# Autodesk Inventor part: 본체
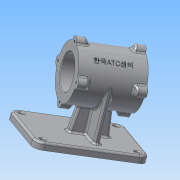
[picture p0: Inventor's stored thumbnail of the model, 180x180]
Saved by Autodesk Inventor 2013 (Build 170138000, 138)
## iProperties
Created: 2015-12
Part Number: 본체
Material: 알루미늄 6061
Document SubType Name: Modeling
Designer: Administrator
Density: 2.71 g/cm^3
Mass: 1165.53 g
Surface Area: 815.593 cm^2
Volume: 430.083 cm^3
Author: Administrator
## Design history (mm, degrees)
sketch "스케치1"
  geometry: L1 (-70, -55)-(70, -55); L2 (70, -55)-(70, 55); L3 (70, 55)-(-70, 55); L4 (-70, 55)-(-70, -55); L5 (-70, -55)-(70, 55); L6 (70, -55)-(-70, 55); 1 further point
  constraints: 12 end point, 2 midpoint, 2 parallel, 1 horizontal, 1 perpendicular
  dimensions: "d0" = 140 distance of L3.end L2.end; "d1" = 110 distance of L2.end L1.end
extrude "돌출1" new body sketch "스케치1" distance "d2" = 10; taper "d3" = 0 deg
node "작업 평면2"
sketch "스케치2"
  geometry: L1 (55, 0)-(-55, 0) reference; C1 r 37 at (0, 80); 2 further points
  constraints: 1 centre point, 1 midpoint, 1 vertical alignment
  dimensions: "d6" = 74 diameter of C1; "d8" = 80 distance from line of L1 C1.centre
extrude "돌출2" join sketch "스케치2" stored distance "d9" = 85; taper "d10" = 0 deg
sketch "스케치3"
  geometry: L1 (-52.5, 117)-(-52.5, 43) reference; L2 (32.5, 43)-(32.5, 117) reference; L3 (-52.5, 80)-(32.5, 80); L4 (-52.5, 103.5)-(-30.8, 103.5); L5 (-30.5, 103.2)-(-30.5, 101); L6 (-30.5, 101)-(10.5, 101); L7 (10.5, 101)-(10.5, 103.2); L8 (10.8, 103.5)-(32.5, 103.5); A1 r 0.3 centre (-30.8, 103.2) between (-30.5, 103.2) and (-30.8, 103.5); A2 r 0.3 centre (10.8, 103.2) between (10.8, 103.5) and (10.5, 103.2); 3 further points
  constraints: 12 end point, 6 point on line, 4 point on circle, 4 tangent, 3 parallel, 2 centre point, 2 collinear, 2 midpoint, 2 perpendicular, 1 equal radius
  dimensions: "d11" = 22 distance of L4.start point (-30.5, 103.5); "d13" = 22 distance of point (10.5, 103.5) L8.end; "d14" = 47 diameter of L8 L3; "d15" = 42 diameter of L6 L3; "d16" = 0.3 radius of A1
revolve "회전1" sketch "스케치3" stored, may be unused: angle "d17" = 90 deg
chamfer "모따기1" distance "d18" = 1; stored, may be unused: second distance "d19" = 2, angle "d20" = 45 deg
sketch "스케치4"
  geometry: L1 (70, 55)-(-70, 55) reference; L2 (-70, 55)-(-70, -55) reference; C1 r 4 at (-58, 43); C2 r 4 at (-58, -43); C3 r 4 at (58, -43); C4 r 4 at (58, 43); 1 further point
  constraints: 4 centre point, 2 horizontal alignment, 2 vertical alignment
  dimensions: "d21" = 8 diameter of C1; "d22" = 8 diameter of C2; "d23" = 8 diameter of C3; "d24" = 8 diameter of C4; "d25" = 12 distance from line of L1 C1.centre; "d26" = 12 distance from line of L2 C1.centre; "d27" = 116 distance of C4.centre C1.centre; "d28" = 86 distance of C1.centre C2.centre
extrude "돌출3" cut sketch "스케치4" stored distance "d29" = 85; taper "d30" = 0 deg
node "작업 평면3"
sketch "스케치5"
  geometry: L1 (0, 37)-(-70, 37); L2 (-70, -55)-(-70, 55) reference; L3 (0, -37)-(-70, -37); L4 (-70, 37)-(-70, -37); A1 r 37 centre (0, 0) between (0, 37) and (0, -37) reference; A2 r 37 centre (0, 0) between (0, 37) and (0, -37); 1 further point
  constraints: 6 end point, 4 point on circle, 2 point on line, 1 centre point, 1 coincident, 1 concentric, 1 horizontal, 1 parallel, 1 perpendicular, 1 tangent, 1 vertical alignment
sketch "스케치7"
  geometry: L1 (70, 10)-(-70, 10) reference; L2 (32.5, 43)-(-52.5, 43) reference; L3 (15, 10)-(10, 50.722); L4 (10, 50.722)-(-30, 50.722); L5 (-30, 50.722)-(-35, 10); L6 (-35, 10)-(15, 10); 3 further points
  constraints: 8 end point, 2 midpoint, 2 parallel, 2 point on line, 1 equal length, 1 vertical alignment
  dimensions: "d40" = 97 deg angle of L1 L5; "d41" = 50 distance of L3.start L5.end; "d43" = 40 distance of L3.end L4.end
sketch "스케치8"
  geometry: A1 r 37 centre (0, 0) between (-37, 0) and (-36.338, -6.969) reference; A2 r 7 centre (-37, 0) between (-36.338, 6.969) and (-36.338, -6.969); 1 further point
  constraints: 5 point on circle, 1 centre point, 1 horizontal alignment
  dimensions: "d46" = 14 diameter of A2
extrude "돌출6" join sketch "스케치8" distance "d47" = 15; taper "d48" = 0 deg
node "작업 평면4"
sketch "스케치11"
  geometry: L1 (10.5, 101)-(10.5, 59) reference; L2 (-30.5, 101)-(-30.5, 59) reference; L3 (-30.5, 80)-(10.5, 80); L4 (17.5, 117)-(-37.5, 117) reference; L5 (-52.5, 124)-(-37.5, 124) reference; L6 (17.5, 124)-(32.5, 124) reference; L7 (-37.5, 117)-(-40.048, 124); L8 (-40.048, 124)-(20.048, 124); L9 (17.5, 117)-(20.048, 124); L10 (17.5, 116.338)-(17.5, 124) reference; L11 (17.5, 117)-(-37.5, 117); 1 further point
  constraints: 10 end point, 2 midpoint, 2 point on line, 1 collinear
  dimensions: "d55" = 110 deg angle of L11 L7; "d56" = 110 deg angle of L4 L9
revolve "회전2" sketch "스케치11" stored, may be unused: angle "d57" = 90 deg
hole "구멍1" diameter "d60" = 3.242; stored, may be unused: countersink angle "d64" = 90 deg, drill point angle "d66" = 118 deg; dims "d58" = 10, "d59" = 10, "d61" = 9, "d62" = 4, "d63" = 2, "d65" = 11
node "작업 평면5"
fillet "모깎기1" dims "d70" = 12
extrude "돌출7" join sketch "스케치7" stored distance "d71" = 12; taper "d72" = 0 deg
extrude "돌출8" join sketch "스케치5" stored distance "d73" = 8; taper "d74" = 0 deg
fillet "모깎기2" dims "d75" = 3
fillet "모깎기3" dims "d76" = 3
fillet "모깎기4" dims "d77" = 3
fillet "모깎기5" dims "d78" = 3
fillet "모깎기6" dims "d79" = 3
fillet "모깎기7" dims "d80" = 3
fillet "모깎기8" dims "d81" = 3
sketch "스케치12"
  geometry: L1 (-106.163, -26.163)-(-80, 0); L2 (-10, 43)-(-10, -43) reference; C1 r 1.621 at (-43, 0) reference; C2 r 1.621 at (-80, -37) reference; C3 r 1.621 at (-117, 0) reference; C4 r 1.621 at (-80, 37) reference; C5 r 24.5 at (-80, 0) reference; A1 r 37 centre (-80, 0) between (-115.862, -9.104) and (-89.104, -35.863) reference; A2 r 3 centre (-89.842, -38.77) between (-86.889, -38.239) and (-89.104, -35.863) reference; A3 r 7 centre (-80, -37) between (-86.889, -38.239) and (-73.111, -38.239) reference; A4 r 3 centre (-70.158, -38.77) between (-70.896, -35.863) and (-73.111, -38.239) reference; A5 r 37 centre (-80, 0) between (-70.896, -35.863) and (-44.138, -9.104) reference; A6 r 3 centre (-41.23, -9.842) between (-41.761, -6.889) and (-44.138, -9.104) reference; A7 r 7 centre (-43, 0) between (-41.761, -6.889) and (-41.761, 6.889) reference; A8 r 3 centre (-41.23, 9.842) between (-44.138, 9.104) and (-41.761, 6.889) reference; A9 r 37 centre (-80, 0) between (-44.138, 9.104) and (-70.896, 35.863) reference; A10 r 3 centre (-70.158, 38.77) between (-73.111, 38.239) and (-70.896, 35.863) reference; A11 r 7 centre (-80, 37) between (-73.111, 38.239) and (-86.889, 38.239) reference; A12 r 3 centre (-89.842, 38.77) between (-89.104, 35.863) and (-86.889, 38.239) reference; A13 r 37 centre (-80, 0) between (-89.104, 35.863) and (-115.862, 9.104) reference; A14 r 3 centre (-118.77, 9.842) between (-118.239, 6.889) and (-115.862, 9.104) reference; A15 r 7 centre (-117, 0) between (-118.239, 6.889) and (-118.239, -6.889) reference; A16 r 3 centre (-118.77, -9.842) between (-115.862, -9.104) and (-118.239, -6.889) reference; 1 further point
  constraints: 2 end point, 1 point on circle
  dimensions: "d82" = 45 deg angle of L2 L1
node "작업 평면6"
sketch "스케치13"
  geometry: L1 (-85, 18.921)-(-85, -18.921) reference; 3 further points
  constraints: 1 horizontal alignment, 1 midpoint, 1 other
  dimensions: "d83" = 42.5 distance from line of L1 point (-42.5, 0)
feature "엠보싱1" sketch "스케치13" dims "d84" = 0.5, "d85" = 0
chamfer "모따기2" distance "d86" = 1; stored, may be unused: second distance "d87" = 2, angle "d88" = 45 deg
node "솔리드1"
pattern_circular "원형 패턴1" dims angle "d53" = 360 deg
mirror "대칭1"
pattern_circular "원형 패턴2" dims angle "d68" = 360 deg
mirror "대칭2"
